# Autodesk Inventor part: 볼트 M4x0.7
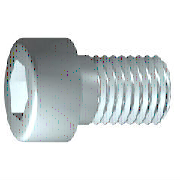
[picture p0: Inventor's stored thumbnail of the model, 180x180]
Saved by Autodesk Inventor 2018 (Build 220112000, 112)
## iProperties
IsCustomPart: 1
Created: 2015-10
Part Number: 볼트 M4x0.7
Material: 스테인리스강
Description: 6각머리 태핑 나사
Document SubType Name: Modeling
Standard: KS B 1003
Designer: mdu
Standards Organization: KS
Language: ko-KR
Size Designation: M 4 x 16
Categories: <MemberInstance><Categories><Category DisplayName="조임쇠" InternalName="e4da775c-781d-43d5-af7c-5136215cf5a6" Mnemonic="FSTN"><Category DisplayName="볼트" InternalN
Density: 8.08 g/cm^3
Mass: 2.70334 g
Surface Area: 3.81118 cm^2
Volume: 0.334572 cm^3
Appearance: 반광택
Author: mdu
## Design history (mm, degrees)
sketch "스케치1"
  geometry: L1 (-1, 0)-(14, 0); L2 (14, 0)-(14, 2); L3 (14, 2)-(1.75, 2); L4 (1.75, 2)-(1.32, 2); L5 (1.32, 2)-(0, 2); L6 (0, 2)-(0, 3.5); L7 (0, 3.5)-(-4, 3.5); L8 (-4, 3.5)-(-4, 1.732); L9 (-4, 1.732)-(-2, 1.732); L10 (-2, 1.732)-(-1, 0); L11 (-7.6, 0)-(17.6, 0) reference; L12 (0, -0.7)-(0, 4.2) reference; L13 (1.75, 2)-(0, 2)
  constraints: 22 end point, 6 parallel, 2 collinear, 2 perpendicular, 1 horizontal, 1 point on line
  dimensions: "d1" = 12.25 distance from line of L3.end L2 (= GEL); "d2" = 0.42952 distance of L4.end L3.end (computed from GAL); "d3" = 4 distance between parallel lines of L8 L6 (= KOH); "d4" = 2 distance of L8.end L9.end (= INTI); "d5" = 60 deg angle of L10 L1; "d6" = 4 diameter of L3 L1 (= GD); "d7" = 4 diameter of L5 L1 (= BDM); "d8" = 3.4641 diameter of L9 L1 (= 1.1547 x SW); "d9" = 7 diameter of L7 L1 (= KOD); "d26" = 14 distance between parallel lines of L12 L2 (= NLG)
revolve "본체" sketch "스케치1" stored, may be unused: angle "d10" = 90 deg
sketch "스케치2"
  geometry: L1 (0, -4.9)-(0, 4.9) reference; L2 (-4.9, 0)-(4.9, 0) reference; L3 (1.732, 0)-(0.866, -1.5); L4 (0.866, -1.5)-(-0.866, -1.5); L5 (-0.866, -1.5)-(-1.732, 0); L6 (-1.732, 0)-(-0.866, 1.5); L7 (-0.866, 1.5)-(0.866, 1.5); L8 (0.866, 1.5)-(1.732, 0); 2 further points
  constraints: 12 end point, 1 coincident, 1 horizontal alignment, 1 point on line, 12 other
extrude "슬롯" join sketch "스케치2" stored distance "d11" = 10; taper "d12" = 0 deg
workplane "Work Plane1"
fillet "Fillet2" dims "d30" = 0.1 (= R)
body "Solid1"
fillet "모깎기1" dims "d17" = 0.4 (= RR)
feature "스레드" dims "d13" = 12.25 (= GEL), "d14" = 0
chamfer "모따기1" distance "d15" = 0.42941 (= -0.5 x SPD + 0.5 x GD); stored, may be unused: second distance "d16" = 0.42941 (= GUL), angle "d27" = 45 deg
other parameters: "GD" = 4 (= NND) [user parameter; used in 2 equation terms], "NLG" = 14 [user parameter; used in 1 equation term], "GEL" = 12.25 [user parameter; used in 2 equation terms], "KOD" = 7 [user parameter; used in 1 equation term], "KOH" = 4 [user parameter; used in 1 equation term], "INTI" = 2 [user parameter; used in 1 equation term], "GAL" = 0.42941 (= 0.61345 x PTC) [user parameter; used in 1 equation term], "GUL" = 0.42941 (= 0.61345 x PTC) [user parameter; used in 1 equation term], "BDM" = 4 (= NND) [user parameter; used in 1 equation term], "SW" = 3 [user parameter; used in 2 equation terms], "RR" = 0.4 [user parameter; used in 1 equation term], "SPD" = 3.14117 (= NND - 1.2269 x PTC) [user parameter; used in 1 equation term], "d19" = 0, "d28" = 0, "d29" = 0, "R" = 0.1 [user parameter; used in 1 equation term], "PHH" = 0.2 [user parameter], "GD1" = 3.14117 (= THREADDIA - 1.2269 x PTC) [user parameter], "THREADDIA" = 4 [user parameter; used in 1 equation term], "FAWI" = 45 deg [user parameter], "TPU" = 14.28571 (computed from PTC) [user parameter], "PTC" = 0.7 [user parameter; used in 5 equation terms], "NND" = 4 [user parameter; used in 3 equation terms], "TOA" = 30 deg [user parameter], "E0" = 3.465 (= 1.155 x SW) [user parameter]
